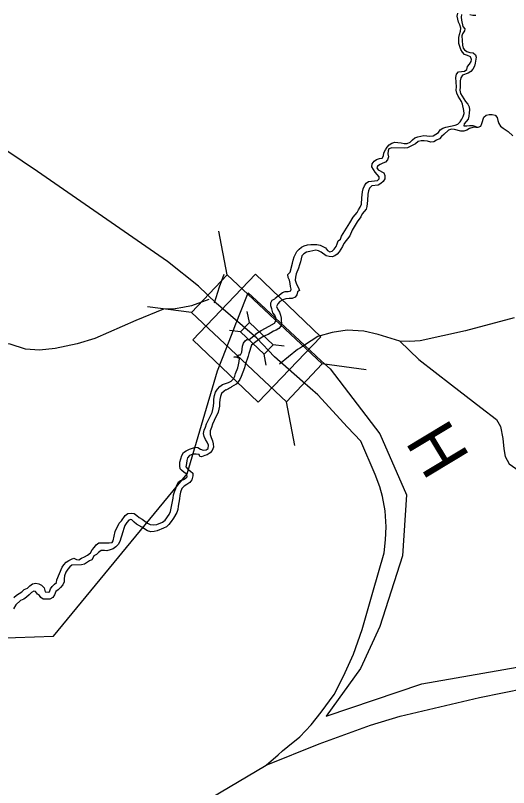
# Model space of a CAD drawing. Extents: x 1945482 to 2853149, y 66427 to 1015778.
# Drawn here: x 2326825 to 2329309, y 137547 to 141437 of the extents above; entities that cross this region are included whole.
import ezdxf

# ---------------------------------------------------------------- set-up
doc = ezdxf.new("R2010")
doc.units = 0
for name, color, linetype in [('Old_Level_22', 7, 'Continuous'), ('Old_Level_31', 7, 'Continuous'), ('Old_Level_32', 7, 'Continuous'), ('Old_Level_35', 7, 'Continuous'), ('Old_Level_50', 7, 'Continuous'), ('Old_Level_59', 7, 'Continuous'), ('Old_Level_60', 7, 'Continuous')]:
    doc.layers.add(name, color=color, linetype=linetype)

msp = doc.modelspace()

# ---------------------------------------------------------------- linework, layer by layer
at = {"layer": 'Old_Level_31'}
msp.add_lwpolyline([(2327718.4, 139803.8), (2328033.6, 140133.2), (2328363.3, 139817.8), (2328048.1, 139488.3)], close=True, dxfattribs=at)
at = {"layer": 'Old_Level_32'}
for points in [[(2328087.5, 137661.1), (2328148.5, 137711.9), (2328170.8, 137732.1), (2328224.6, 137776.9), (2328247, 137794.8), (2328258.2, 137803.8), (2328315.1, 137864.2), (2328364.8, 137927.9), (2328430.1, 138016.6), (2328478.3, 138108.3), (2328528.1, 138220.3), (2328571.6, 138343.2), (2328626, 138531.6), (2328682, 138730.7), (2328689.7, 138796), (2328692.9, 138861.3), (2328688.2, 138942.2), (2328674.5, 139013.3), (2328661.1, 139062.6), (2328636.5, 139125.3), (2328565.2, 139292.4), (2328498.3, 139362.7), (2328347.7, 139526.7), (2328271.1, 139593.2), (2328130.1, 139716.7), (2328040.8, 139810.8)], [(2328087.5, 137661.1), (2328354.4, 137767.9), (2328614, 137861.1), (2328763.5, 137906.7), (2328877.3, 137933.9), (2329162.4, 138001.2), (2329510.6, 138071.2), (2329826.2, 138127.2), (2330305.4, 138212.7), (2330734.5, 138293.6), (2331336.7, 138411.8), (2331817.1, 138503.6), (2332148.2, 138564.2), (2332304.8, 138595.7), (2332717.4, 138677.3), (2332882, 138707.3), (2332990.1, 138729.5), (2333073.9, 138740)], [(2326327.3, 135117.9), (2326341.9, 135223.4), (2326366.5, 135382.4), (2326411.3, 135684.8), (2326444.9, 135868.5), (2326480.7, 136121.6), (2326530, 136437.4), (2326544.2, 136542.8), (2326561.8, 136624.8), (2326585.6, 136690.1), (2326612.6, 136745), (2326631.2, 136775.1), (2326644.7, 136790.7), (2326681, 136830.1), (2326723.5, 136868.4), (2326790.9, 136915.1), (2326932.9, 137008.6), (2327259.7, 137194.5), (2327808.2, 137494.7), (2328087.5, 137661.1)]]:
    msp.add_lwpolyline(points, dxfattribs=at)
at = {"layer": 'Old_Level_35'}
msp.add_line((2328281, 139776.5), (2328260.2, 139763.2), dxfattribs=at)
for points in [[(2328040.8, 139810.8), (2327836.4, 139987.2), (2327747.2, 140074), (2327590.5, 140197.2), (2326936, 140651.4), (2326703.5, 140807.1), (2326576.8, 140868.3), (2326111.2, 141105.9), (2325826.1, 141234.8), (2325346.2, 141478.1)], [(2327874.6, 140132.8), (2327851, 140068.3), (2327825.9, 139987.2)], [(2327799.3, 140006.2), (2327712.5, 139974.9), (2327668.6, 139966.7)], [(2327668.6, 139966.7), (2327629.1, 139959.4), (2327571.1, 139957.2), (2327431.3, 139899.8), (2327224.8, 139809.6), (2327136, 139782.1), (2327024.9, 139759.7), (2326947.2, 139750.7), (2326876.7, 139755.8), (2326798, 139780.6), (2326737.6, 139788.3), (2326577.9, 139776.1), (2326329, 139746.3), (2326078.1, 139716.3), (2325908.6, 139705.7), (2325750.7, 139697.2), (2325710.4, 139703.8), (2325673.7, 139728.3)], [(2329337.6, 139913.1), (2329092, 139849.2), (2328864, 139798.2), (2328810, 139794.1), (2328762, 139796.1)], [(2328762, 139796.1), (2328652.7, 139829.9), (2328579.8, 139847), (2328495.6, 139851.9), (2328420.2, 139840.7), (2328348.8, 139819.8), (2328281, 139776.5)], [(2328260.2, 139763.2), (2328245.4, 139753.7), (2328154.5, 139680.2)], [(2328762, 139796.1), (2328857.5, 139704.1), (2329020.8, 139576.3), (2329169.3, 139462.4), (2329247.9, 139401.5), (2329269, 139366.2), (2329279.5, 139306.6), (2329285.5, 139254.6), (2329291, 139215.1), (2329312.5, 139177.9), (2329362.1, 139143.7), (2329541, 139018.9), (2329739.6, 138902.7), (2329920.2, 138791.6), (2329992.3, 138736.4), (2330065.1, 138663.5), (2330120.9, 138621.7), (2330292.5, 138580.2), (2330460.9, 138570.8), (2330477.4, 138571.1)]]:
    msp.add_lwpolyline(points, dxfattribs=at)
at = {"layer": 'Old_Level_50'}
for p, q in [((2327892, 140131.2), (2327848.9, 140350.4)), ((2327955.6, 139934.4), (2327989.9, 140022.3)), ((2327712, 139940.2), (2327490.7, 139970.1)), ((2328060.4, 139981.7), (2328281, 139776.5)), ((2327940.7, 139896), (2327955.6, 139934.4)), ((2328003.6, 139890.9), (2327992.8, 139945.7)), ((2327925.4, 139856.9), (2327937.8, 139888.8)), ((2327937.8, 139888.8), (2327940.7, 139896)), ((2327886.7, 139757.7), (2327925.4, 139856.9)), ((2327958.6, 139843.1), (2327903.3, 139850.6)), ((2328178.4, 139771), (2328123, 139778.4)), ((2328281, 139776.5), (2328367.1, 139696.3)), ((2328088.8, 139675.9), (2328078, 139730.7)), ((2328591, 139651.5), (2328369.6, 139681.4)), ((2328232.8, 139271.2), (2328189.7, 139490.3))]:
    msp.add_line(p, q, dxfattribs=at)
msp.add_lwpolyline([(2327712, 139940.2), (2328189.7, 139490.3), (2328369.6, 139681.4), (2327892, 140131.2)], close=True, dxfattribs=at)
for points in [[(2327989.9, 140022.3), (2327997.1, 140040.6), (2328060.4, 139981.7)], [(2327958.6, 139843.1), (2328078, 139730.7), (2328123, 139778.4), (2328003.6, 139890.9), (2327958.6, 139843.1)], [(2325275.5, 138098.8), (2325489.4, 138089.5), (2325672, 138031.8), (2325864.1, 138185.6), (2326065.9, 138233.6), (2326277.3, 138147.1), (2326728.8, 138300.9), (2327017.1, 138310.5), (2327689.6, 139127.5), (2327843.3, 139646.6), (2327886.7, 139757.7)], [(2328367.1, 139696.3), (2328410.2, 139656.2), (2328660, 139329.4), (2328794.5, 139021.8), (2328775.3, 138714.2), (2328660, 138358.6), (2328563.9, 138147.1), (2328391, 137906.8), (2328871.4, 138070.2), (2330139.6, 138291.3), (2331049.1, 138487.4)]]:
    msp.add_lwpolyline(points, dxfattribs=at)
at = {"layer": 'Old_Level_59'}
msp.add_lwpolyline([(2329143.7, 140874), (2329156.5, 140874.1), (2329168.7, 140879), (2329174.2, 140893.6), (2329184, 140924.1), (2329196, 140935.2), (2329211, 140938.1), (2329226.5, 140937.8), (2329242, 140934.9), (2329251, 140923.4), (2329254.2, 140907.8), (2329259.2, 140892.6), (2329268.7, 140878.7), (2329281.2, 140868.6), (2329307.7, 140852.3), (2329330, 140830.4)], dxfattribs=at)
at = {"layer": 'Old_Level_60'}
for points in [[(2328500.5, 140379.3), (2328510.2, 140393.3), (2328525.5, 140421.8), (2328545.7, 140445.3), (2328553, 140458.6), (2328562, 140471.9), (2328567.5, 140486.9), (2328570, 140518.7), (2328573.5, 140549.5), (2328576, 140564.4), (2328583, 140578.8), (2328591.5, 140592.2), (2328603.5, 140600.8), (2328619, 140603.1), (2328634.2, 140603.8), (2328649.5, 140606.1), (2328658, 140614.8), (2328657.2, 140624.1), (2328636.5, 140647.7), (2328620, 140674.7), (2328622.5, 140689.7), (2328631.2, 140702.8), (2328644, 140711.4), (2328658.7, 140715.9), (2328672.7, 140717.7), (2328679, 140729.4), (2328681.2, 140745.8), (2328688.5, 140760.1), (2328696.7, 140773.4), (2328708.2, 140785.4), (2328721, 140793.6), (2328736.2, 140798.3), (2328752, 140797.8), (2328768.2, 140795.7), (2328783, 140792.5), (2328798.2, 140792.7), (2328812.7, 140799.3), (2328825, 140810.6), (2328837.2, 140819.9), (2328851.7, 140825.2), (2328882.2, 140832.1), (2328898, 140831.3), (2328912.7, 140828.5), (2328928.5, 140831.5), (2328943, 140838.8), (2328955.7, 140847), (2328963.7, 140860.3), (2328977.2, 140869.2), (2328992.5, 140874), (2329040, 140884.5), (2329054, 140890), (2329066, 140901.2), (2329073.7, 140914.5), (2329080.5, 140928.6), (2329085, 140943.3), (2329084, 140959.1), (2329077.5, 140989.5), (2329071.2, 141004.1), (2329064.2, 141017.6), (2329055, 141030.8), (2329047.7, 141046), (2329044.7, 141061.4), (2329047.5, 141077.3), (2329042.5, 141124.9), (2329046.2, 141140.7), (2329056, 141152.7), (2329071.7, 141154.9), (2329087, 141156), (2329099, 141164.2), (2329102, 141179.3), (2329111.7, 141191.7), (2329120.2, 141204.7), (2329123, 141215.1), (2329116.7, 141229.3), (2329102.5, 141235.3), (2329087.5, 141239.9), (2329076.7, 141251.8), (2329069.2, 141266), (2329063, 141280.4), (2329059, 141295.6), (2329058.2, 141311.9), (2329058.7, 141327), (2329062, 141341.9), (2329067, 141357.3), (2329068.2, 141373.4), (2329064, 141389.5), (2329056.7, 141403.3), (2329053, 141417.9), (2329050.7, 141433.6), (2329052.7, 141448.9)], [(2329072.2, 141442.2), (2329070.2, 141428.5), (2329072.2, 141412.7), (2329078.5, 141381.9), (2329088.2, 141370.4), (2329086.5, 141359.4), (2329077.2, 141345.4), (2329074, 141334.4), (2329077.7, 141288), (2329080, 141272.8), (2329086.5, 141264.4), (2329099, 141255.2), (2329114.2, 141250.9), (2329130, 141248.9), (2329142.5, 141239.2), (2329146, 141227.8), (2329141, 141196.3), (2329137, 141181.2), (2329128.5, 141167.1), (2329118.7, 141155.2), (2329106, 141146.4), (2329077, 141135.8), (2329068.7, 141123), (2329064.5, 141107.4), (2329064.5, 141076.8), (2329063.5, 141061.1), (2329067.5, 141044.6), (2329075, 141029.8), (2329083.2, 141016.4), (2329092.5, 141003.2), (2329103, 140990.6), (2329110, 140977), (2329111.5, 140962), (2329111.2, 140946), (2329109, 140930.4), (2329105, 140915.6), (2329096, 140902.5), (2329084.7, 140892), (2329084.2, 140881.3), (2329098, 140880.5), (2329113, 140883.3), (2329128.5, 140882.5), (2329143.5, 140878.2), (2329143.7, 140874)], [(2329144.5, 141437.7), (2329129.5, 141437.3), (2329114, 141440.7)], [(2329143.7, 140874), (2329128.5, 140872.8), (2329113, 140867.4), (2329099, 140860.1), (2329083.2, 140854.5), (2329068.2, 140854.1), (2329037.2, 140863.4), (2329021.7, 140864.2), (2329006.5, 140859.3), (2328983.5, 140837.5), (2328971, 140827.5), (2328960.7, 140815.6), (2328945.5, 140809.7), (2328932.7, 140799.8), (2328917, 140799), (2328900.7, 140803.5), (2328884.5, 140805.1), (2328869, 140805.3), (2328853.5, 140801.5), (2328840.2, 140791.2), (2328827, 140783.7), (2328799.2, 140769.8), (2328784.2, 140768.3), (2328721.2, 140771.1), (2328706.5, 140765.8), (2328701.7, 140755.7), (2328701.2, 140740), (2328704.2, 140724.6), (2328699.7, 140710), (2328689.7, 140697.5), (2328675.2, 140693.4), (2328661.7, 140686.7), (2328649.5, 140677.3), (2328646, 140670.4), (2328652.2, 140659.5), (2328680.5, 140643.6), (2328686.5, 140630.7), (2328686.2, 140614.9), (2328677.5, 140601), (2328665, 140589.9), (2328651.5, 140582.3), (2328620, 140578.8), (2328609, 140567.5), (2328603.2, 140553.2), (2328600.7, 140537.6), (2328598.7, 140505.8), (2328596.5, 140490.6), (2328595.2, 140475.2), (2328592.5, 140461), (2328582, 140449.6), (2328572.2, 140437.1), (2328565.2, 140423.5), (2328546.2, 140396.9), (2328522, 140356.3), (2328509, 140326.7), (2328479.7, 140287.8), (2328472.5, 140273.6), (2328455, 140246.4), (2328445.5, 140234.8), (2328433.2, 140225.5), (2328420.5, 140220.9), (2328405.5, 140222.4), (2328390.5, 140226.2), (2328364.7, 140244.5), (2328351.2, 140251.3), (2328338.2, 140255), (2328307.7, 140248.7), (2328291.7, 140243.9), (2328278.2, 140237.1), (2328268, 140226.8), (2328261.5, 140195.9), (2328256, 140180.7), (2328251.5, 140164.9), (2328239.5, 140134.9), (2328235.5, 140119.6), (2328233.5, 140104), (2328239.5, 140088.6), (2328253.2, 140060.2), (2328255.2, 140052.4), (2328245.7, 140045.6), (2328241.7, 140030), (2328233.5, 140017.2), (2328218.5, 140011.6), (2328203.5, 140011.4), (2328187.5, 140009.9), (2328171.2, 140005.2), (2328157.7, 139995.5), (2328146, 139984.7), (2328139.7, 139970.3), (2328146.5, 139955.2), (2328154.5, 139941.8), (2328159.5, 139927), (2328163.7, 139911.8), (2328164.5, 139875.6)], [(2327672, 139234.9), (2327685.7, 139244.5), (2327701.2, 139252.6), (2327732, 139262.8), (2327743.5, 139261.4), (2327758, 139253), (2327771.5, 139246.7), (2327786.7, 139248.6), (2327796.7, 139256.4), (2327798.2, 139271.8), (2327791.5, 139287.3), (2327783.2, 139300.6), (2327775, 139316), (2327771.7, 139331.4), (2327776.2, 139347.6), (2327782.5, 139363.7), (2327787.2, 139379.1), (2327816.5, 139437.8), (2327820, 139452), (2327822.5, 139469.1), (2327824.7, 139488.1), (2327825.2, 139504.8), (2327828.5, 139523.1), (2327833.7, 139539.8), (2327842.7, 139554.9), (2327855.5, 139567.9), (2327868.5, 139577.8), (2327883.5, 139582.3), (2327899, 139588.3), (2327912.5, 139595.5), (2327923.5, 139606.1), (2327930, 139619.6), (2327934, 139634.1), (2327944.7, 139662.5), (2327948, 139677.9), (2327952.5, 139693.1), (2327954.5, 139708.4), (2327941.7, 139713.7), (2327926.2, 139715.9), (2327926, 139717.6), (2327941.2, 139717.7), (2327946.2, 139720), (2327948.2, 139727.7), (2327959.2, 139727.3), (2327965.7, 139741.1), (2327969.5, 139771.6), (2327974.2, 139785.9), (2327982.5, 139798.6), (2327990, 139804), (2328000, 139802.8), (2328035.5, 139832.2), (2328035.7, 139833.7), (2328063, 139849.8), (2328104, 139871.9), (2328130.2, 139887.3), (2328136.7, 139899.2), (2328136.7, 139914.4), (2328131.2, 139927.1), (2328121.2, 139938.7), (2328116, 139960), (2328111.2, 139974.7), (2328111, 139989.2), (2328118.5, 140002.2), (2328131.7, 140009.9), (2328133, 140013.1), (2328169.5, 140041.3), (2328184.2, 140046.6), (2328199.7, 140046.4), (2328211.7, 140050.7), (2328213.2, 140057.7), (2328210.2, 140072.5), (2328208.2, 140087.7), (2328205, 140103.3), (2328199.5, 140117.2), (2328197.5, 140132.5), (2328209.2, 140143.2), (2328221.5, 140188.9), (2328224.5, 140205), (2328229, 140220.4), (2328235, 140234.3), (2328242.7, 140247.5), (2328253.7, 140259.2), (2328266, 140269.3), (2328280.2, 140276.9), (2328296, 140281.4), (2328312.2, 140284.1), (2328343.5, 140283.6), (2328359.5, 140279.5), (2328387.5, 140266.4), (2328396.5, 140253.7), (2328408.2, 140245.6), (2328420.2, 140249.9), (2328431.2, 140260.6), (2328440.5, 140272.6), (2328446, 140286.7), (2328450.2, 140301), (2328461.7, 140310.9), (2328468.2, 140324.9), (2328485, 140351.5), (2328500.5, 140379.3)], [(2328164.5, 139875.6), (2328162.5, 139871.4), (2328151.7, 139860.8), (2328139, 139851.7), (2328125, 139846.2), (2328098.5, 139830.3), (2328084.5, 139824.5), (2328071, 139817.4), (2328058, 139809.1), (2328013.5, 139777), (2328000, 139735), (2327997, 139720.1), (2327983, 139676.4), (2327979.5, 139661.3), (2327962.2, 139618), (2327955.2, 139604), (2327947.2, 139590.8), (2327937, 139579.8), (2327913, 139565.8), (2327910, 139562.6), (2327903.5, 139559.8), (2327898.2, 139555.9), (2327885.2, 139549.1), (2327885, 139550.6), (2327876, 139545), (2327863.7, 139533.3), (2327858, 139518), (2327855, 139502.9), (2327853, 139484.6), (2327852.5, 139469.4), (2327850, 139454.5), (2327846, 139439.2), (2327826, 139396.3), (2327818.5, 139378), (2327812.7, 139360.9), (2327805.5, 139344.9), (2327806.5, 139326.8), (2327811.7, 139311.2), (2327818.5, 139294.9), (2327821.7, 139279.2), (2327822, 139261.8), (2327815.7, 139245.6), (2327806.5, 139233.2), (2327791.7, 139224), (2327778.7, 139221.1), (2327762, 139212.8), (2327753.5, 139215.3), (2327750, 139226.2), (2327735.7, 139227.1), (2327718.5, 139226.4), (2327701.5, 139221), (2327692.5, 139209.1), (2327688, 139195.3), (2327686.7, 139179.9), (2327683.7, 139162.5), (2327693.7, 139152.2), (2327707, 139142.1), (2327718, 139130.6), (2327718.5, 139117.7), (2327714.2, 139097.4), (2327703.5, 139085.1), (2327689, 139074), (2327675.7, 139065.7), (2327663, 139053.9), (2327656.5, 139036.3), (2327653.2, 139018.7), (2327651, 139002.1), (2327644.2, 138965.1), (2327643.7, 138948.6), (2327637.7, 138933.6), (2327621.5, 138904.5), (2327610, 138887.3), (2327598.5, 138872.9), (2327586, 138861.8), (2327570.7, 138853.7), (2327539.5, 138840.5), (2327524, 138836.7), (2327508, 138836.2), (2327490, 138841), (2327462, 138859.5), (2327434.7, 138875.1), (2327422.7, 138884.9), (2327412, 138895.9), (2327405.7, 138897.5), (2327396.2, 138894.3), (2327385.5, 138883.5), (2327377, 138867.3), (2327371.5, 138853.3), (2327367, 138836.5), (2327351.7, 138787.5), (2327342.7, 138771.2), (2327330.7, 138761), (2327317, 138750.8), (2327302.5, 138745.3), (2327286, 138739.9), (2327274, 138742.1), (2327257, 138741.8), (2327243.7, 138731.8)], [(2327107.2, 138698.6), (2327119.2, 138702.8), (2327132.5, 138695.6), (2327144.7, 138695.3), (2327158.5, 138703.2), (2327173.7, 138709.5), (2327188, 138717.9), (2327202.5, 138729.9), (2327212.2, 138744.3), (2327223.7, 138758.5), (2327232.5, 138770.9), (2327244.7, 138780.5), (2327261.7, 138781), (2327278.5, 138779.9), (2327297, 138780.6), (2327312, 138782.5), (2327316.7, 138789.8), (2327327.2, 138837.6), (2327348.2, 138879.1), (2327360.2, 138890.6), (2327377.2, 138917.8), (2327390.7, 138927.4), (2327408, 138930.4), (2327423.7, 138927.5), (2327437.5, 138917.8), (2327449, 138907.9), (2327463.5, 138900.1), (2327491.2, 138879.7), (2327504.5, 138872.1), (2327519, 138870.4), (2327536.7, 138871.9), (2327566, 138885.3), (2327579.5, 138895.1), (2327599.5, 138923), (2327606, 138938.4), (2327613.7, 138971.6), (2327615.5, 138988.8), (2327619.5, 139005.6), (2327622, 139022.8), (2327626.2, 139037.5), (2327633, 139053.7), (2327638.2, 139070.9), (2327647, 139086.9), (2327656.5, 139093.7), (2327671, 139099.1), (2327685, 139108.2), (2327689.5, 139112.9), (2327688.5, 139125.5), (2327674.7, 139135.2), (2327661, 139146.3), (2327655.5, 139153), (2327654, 139168.3), (2327653.7, 139187), (2327662.7, 139219.8), (2327672, 139234.9)], [(2327243.7, 138731.8), (2327232.7, 138721.5), (2327220.5, 138714.7), (2327216.5, 138706), (2327210, 138695.2), (2327199, 138689.2), (2327173.5, 138673.2), (2327158.2, 138668.8), (2327108.5, 138667.1), (2327099, 138660), (2327088.7, 138647.5), (2327079.5, 138631.8), (2327073, 138614.5), (2327070.2, 138599.5), (2327070.5, 138584.3), (2327064.7, 138568.8), (2327052, 138554.9), (2327040.5, 138544.2), (2327028, 138535.2), (2327022.7, 138518.9), (2327013.5, 138504.4), (2326998.5, 138497.2), (2326964.2, 138496.2), (2326952.5, 138504.5), (2326945.7, 138514.8), (2326937, 138522.4), (2326926.7, 138534.7), (2326917.5, 138537.3), (2326906.2, 138530.8), (2326894.2, 138517.7), (2326880.5, 138505.9), (2326867.7, 138496.2), (2326851.5, 138489.2), (2326826.5, 138467.2), (2326815.7, 138448.2)], [(2326817.2, 138505.4), (2326830.2, 138517), (2326856.7, 138533.8), (2326869.5, 138544.9), (2326886, 138551.3), (2326897, 138564.2), (2326910.7, 138574.3), (2326928.2, 138577.1), (2326943.2, 138574.6), (2326957, 138567.1), (2326970, 138554.3), (2326973, 138539.5), (2326975, 138533.9), (2326991.5, 138531.7), (2326996.5, 138533), (2327002.5, 138548), (2327010.7, 138560.9), (2327021.5, 138572.3), (2327031.7, 138580.6), (2327033, 138594.8), (2327060.5, 138657), (2327069, 138669.9), (2327081.5, 138682.9), (2327094, 138691.6), (2327107.2, 138698.6)]]:
    msp.add_lwpolyline(points, dxfattribs=at)

# ---------------------------------------------------------------- texts
at = {"layer": 'Old_Level_22'}
msp.add_text('H', height=246.1, rotation=301.1059, dxfattribs=at).set_placement((2328784.9, 139289.4))

doc.saveas('drawing.dxf')
